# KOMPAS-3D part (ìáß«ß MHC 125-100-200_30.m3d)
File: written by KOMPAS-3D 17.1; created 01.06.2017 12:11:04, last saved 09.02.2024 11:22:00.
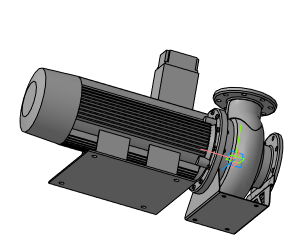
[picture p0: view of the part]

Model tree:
1. Операция без истории:1

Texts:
  ООО АДЛ ГРУПП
